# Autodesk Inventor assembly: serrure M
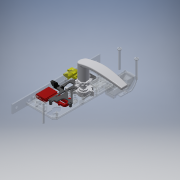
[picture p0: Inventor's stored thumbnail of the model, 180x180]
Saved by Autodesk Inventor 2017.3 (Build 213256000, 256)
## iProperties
Created: 2011-01
Part Number: serrure M
Material: Générique
Document SubType Name: Assembly
Designer: ficho
Sending System: SolidWorks 2009
Last Author: christophe
Last Saved: 2011-02-11
Author: ficho
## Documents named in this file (12)
- G:\travail\année 2019-2020\réforme\toussaint\Serrure biométrique SET\Documentations_pedagogique\Modelisation_Solidworks\serrure M.iam
- G:\travail\année 2019-2020\réforme\toussaint\Serrure biométrique SET\Documentations_pedagogique\Modelisation_Solidworks\porte.iam
- G:\travail\année 2019-2020\réforme\toussaint\Serrure biométrique SET\Documentations_pedagogique\Modelisation_Solidworks\poignee interieure.iam
- G:\travail\année 2019-2020\réforme\toussaint\Serrure biométrique SET\Documentations_pedagogique\Modelisation_Solidworks\axe de noix.ipt
- G:\travail\année 2019-2020\réforme\toussaint\Serrure biométrique SET\Documentations_pedagogique\Modelisation_Solidworks\verrouilleur.ipt
- G:\travail\année 2019-2020\réforme\toussaint\Serrure biométrique SET\Documentations_pedagogique\Modelisation_Solidworks\axe moteur.ipt
- G:\travail\année 2019-2020\réforme\toussaint\Serrure biométrique SET\Documentations_pedagogique\Modelisation_Solidworks\plaque.iam
- G:\travail\année 2019-2020\réforme\toussaint\Serrure biométrique SET\Documentations_pedagogique\Modelisation_Solidworks\pene dormant.iam
- G:\travail\année 2019-2020\réforme\toussaint\Serrure biométrique SET\Documentations_pedagogique\Modelisation_Solidworks\pene lançant.iam
- G:\travail\année 2019-2020\réforme\toussaint\Serrure biométrique SET\Documentations_pedagogique\Modelisation_Solidworks\poussoir.ipt
- G:\travail\année 2019-2020\réforme\toussaint\Serrure biométrique SET\Documentations_pedagogique\Modelisation_Solidworks\guide ressort.ipt
- G:\travail\année 2019-2020\réforme\toussaint\Serrure biométrique SET\Documentations_pedagogique\Modelisation_Solidworks\chambranle.iam
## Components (11 placed, 11 different names)
1. porte:1 [sub-assembly] — Placage:1, Placage:2, Placage:3, Angle:1, Tangente:1, Tangente:2, Tangente:3, Placage:4, Placage:5, Placage:6, Placage:7, Tangente:4, Angle:2
2. poignee interieure:1 [sub-assembly] — Placage:1, Placage:2
3. axe de noix:1
4. verrouilleur:1 — Placage:5, Placage:6
5. axe moteur:1
6. plaque:1 [sub-assembly] — Tangente:2, Tangente:3, Placage:4, Tangente:5
7. pene dormant:1 [sub-assembly] — Placage:7, Tangente:4, Angle:2, Tangente:5
8. pene lançant:1 [sub-assembly] — Placage:3, Angle:1, Tangente:1
9. poussoir:1
10. guide ressort:1
11. chambranle:1 [sub-assembly]
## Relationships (14: Mate 7, Tangent 5, Angle 2)
- Placage:1 [Mate]: porte:1 ↔ poignee interieure:1
- Placage:2 [Mate]: porte:1 ↔ poignee interieure:1
- Placage:3 [Mate]: porte:1 ↔ pene lançant:1
- Angle:1: porte:1 ↔ pene lançant:1
- Tangente:1: porte:1 ↔ pene lançant:1
- Tangente:2: porte:1 ↔ plaque:1
- Tangente:3: porte:1 ↔ plaque:1
- Placage:4 [Mate]: porte:1 ↔ plaque:1
- Placage:5 [Mate]: porte:1 ↔ verrouilleur:1
- Placage:6 [Mate]: porte:1 ↔ verrouilleur:1
- Placage:7 [Mate]: porte:1 ↔ pene dormant:1
- Tangente:4: porte:1 ↔ pene dormant:1
- Angle:2: porte:1 ↔ pene dormant:1
- Tangente:5: plaque:1 ↔ pene dormant:1
